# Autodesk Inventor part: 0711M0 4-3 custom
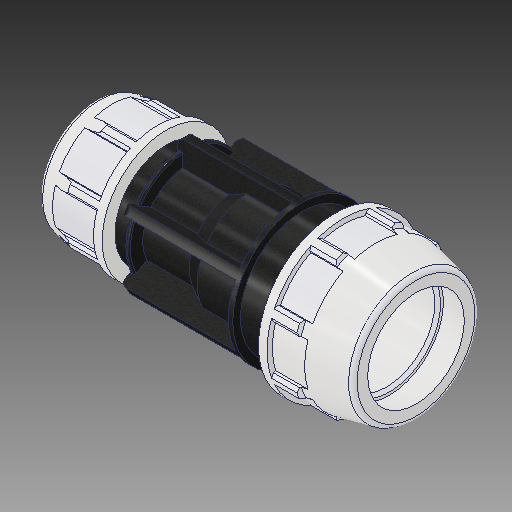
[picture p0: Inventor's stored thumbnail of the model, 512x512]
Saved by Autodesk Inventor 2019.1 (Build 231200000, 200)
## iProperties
Created: 2017-02
Part Number: 0711M0 4-3 custom
Material: PVC-Piping
Description: PLASSON REDUCING COUPLER 4'' - 3''
Document SubType Name: Modeling
Designer: KIM
Mass: 92.6774 g
Surface Area: 199.44 cm^2
Volume: 66.1981 cm^3
Density: 1.4 g/cm^3
Appearance: PTFE
Author: KIM
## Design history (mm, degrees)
derived "0711M0.ipt"
feature "Solid1::0711M0.ipt"
tag "TaggingFeature1"
body "Solid1"
other parameters: "d2" = 114.1, "d4" = 31.5, "d5" = 54, "d7" = 181.102, "d9" = 54, "d11" = 5.4, "d12" = 144.8816, "d13" = 120 deg, "d14" = 148.33, "d15" = 12 deg, "d16" = 162.9918, "d18" = 5.705, "d19" = 35 deg, "d20" = 17.5 deg, "d21" = 168.42486, "d23" = 0, "d25" = 360 deg, "d27" = 3.62204, "d42" = 41.58, "d46" = 3.423, "d51" = 378, "d52" = 130.34483, "d53" = 12 deg, "d54" = 195.072, "d56" = 133.05, "d57" = 88.7, "d58" = 102.69, "d59" = 79.83, "d60" = 136.7028, "d61" = 121.5136, "d62" = 37.8, "d63" = 45.36, "d64" = 120 deg, "d65" = 151.892, "d68" = 27, "d74" = 141.25956, "d75" = 35 deg, "d76" = 17.5 deg, "d78" = 0, "d80" = 360 deg, "d85" = 3.03784, "d88" = 1.774, "d93" = 162, "d94" = 126.7714, "d97" = 2.53523, "d98" = 10.12613, "d99" = 0, "d100" = 7.24408, "d102" = 360 deg, "d104" = 2, "d106" = 0, "d107" = 10.12613, "d108" = 0, "d109" = 10.12613, "d110" = 0, "d_" = 114.1, "E_" = 181.102, "H_" = 378, "l_" = 195.072, "d_1" = 88.7, "E_1" = 151.892, "l_1" = 162, "d96" = 7.6057
